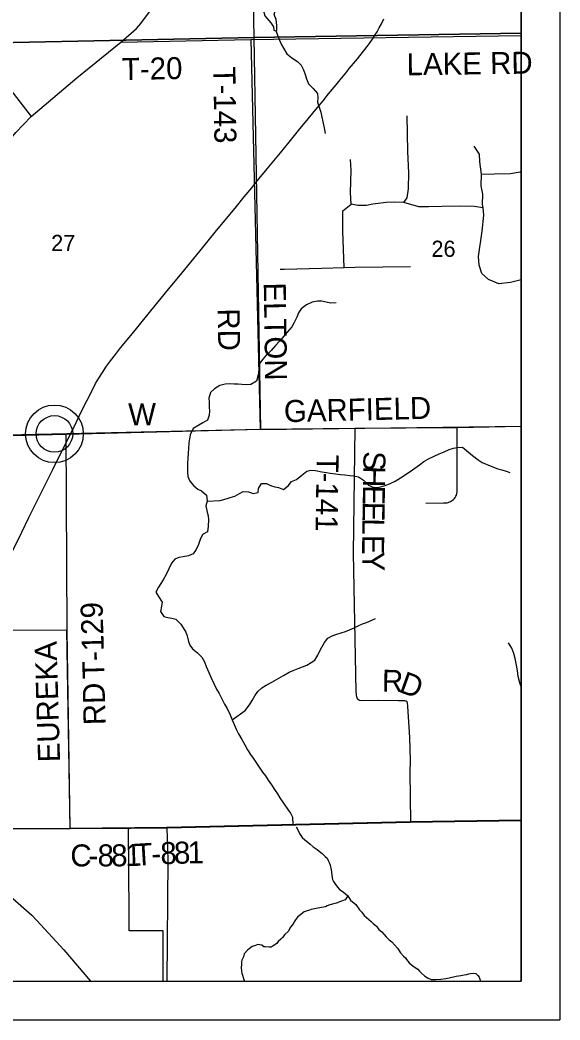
# Model space of a CAD drawing. Extents: x 0 to 36.9, y 0 to 22.
# Drawn here: x 7.606 to 9, y 14 to 16.582 of the extents above; entities that cross this region are included whole.
import ezdxf

# ---------------------------------------------------------------- set-up
doc = ezdxf.new("R2010")
doc.units = 0
for name, color, linetype in [('Default', 7, 'Continuous'), ('GM_X_County_Road', 7, 'Continuous'), ('GM_X_County_Road_Text', 7, 'Continuous'), ('GM_X_Minor_Lake', 7, 'Continuous'), ('GM_X_Minor_River', 7, 'Continuous'), ('GM_X_Rail_Line', 7, 'Continuous'), ('GM_X_Section', 7, 'Continuous'), ('GM_X_Section_Text', 7, 'Continuous'), ('GM_X_State_Route', 7, 'Continuous'), ('GM_X_Township_Road', 7, 'Continuous'), ('GM_X_Township_Road_Text', 7, 'Continuous'), ('GM_X_Unincorporated', 7, 'Continuous'), ('GM_X_Unincorporated_Location', 7, 'Continuous'), ('SH_Cut_Line', 7, 'Continuous'), ('SH_Data', 7, 'Continuous')]:
    doc.layers.add(name, color=color, linetype=linetype)

msp = doc.modelspace()

# ---------------------------------------------------------------- linework, layer by layer
at = {"layer": 'Default'}
for points in [[(8.9, 16.5477), (8.9, 17.5601), (8.1912, 17.5487), (8.21, 16.5368)], [(8.9, 15.5336), (8.9, 16.5477), (8.21, 16.5368), (8.2269, 15.5248)]]:
    msp.add_lwpolyline(points, close=True, dxfattribs=at)
msp.add_lwpolyline([(6.5942, 14.1), (7.9756, 14.1), (7.9756, 14.2298), (7.8885, 14.2299), (7.8885, 14.2755), (7.8862, 14.4955), (7.7356, 14.4946), (7.7276, 15.0066), (7.4716, 15.0059)], dxfattribs=at)
at = {"layer": 'GM_X_County_Road'}
for p, q in [((7.4756, 15.5061), (7.7254, 15.5123)), ((8.6139, 14.511), (8.9, 14.5152)), ((7.4323, 14.4931), (7.7358, 14.4941)), ((7.7358, 14.4941), (7.8934, 14.4956))]:
    msp.add_line(p, q, dxfattribs=at)
for points in [[(7.5431, 17.5191), (7.5334, 17.2126), (7.5226, 16.9418), (7.5085, 16.6619), (7.5038, 16.5816), (7.5026, 16.5512), (7.5032, 16.5386), (7.5044, 16.52), (7.56, 16.4312), (7.6351, 16.3326)], [(7.7254, 15.5123), (8.2259, 15.5257), (8.4702, 15.5284), (8.7347, 15.5299), (8.9, 15.5336)], [(7.8934, 14.4956), (7.9821, 14.4964), (7.986, 14.4965), (8.6139, 14.511)]]:
    msp.add_lwpolyline(points, dxfattribs=at)
at = {"layer": 'GM_X_Minor_Lake'}
msp.add_lwpolyline([(8.2296, 16.6219), (8.2341, 16.6091), (8.2385, 16.5928), (8.2537, 16.5745), (8.2607, 16.5647), (8.2616, 16.556), (8.2696, 16.5535), (8.269, 16.5679), (8.2676, 16.5831), (8.2624, 16.5963), (8.2649, 16.6058), (8.2666, 16.6135), (8.2642, 16.6195)], dxfattribs=at)
at = {"layer": 'GM_X_Minor_River'}
for points in [[(8.2671, 16.5543), (8.2741, 16.5339), (8.2808, 16.5199), (8.2867, 16.509), (8.2953, 16.4948), (8.3081, 16.484), (8.323, 16.4747), (8.3323, 16.465), (8.3382, 16.4534), (8.3423, 16.4409), (8.3455, 16.4296), (8.3507, 16.4168), (8.363, 16.4048), (8.3743, 16.3925), (8.3748, 16.3819), (8.3739, 16.3697), (8.3787, 16.3565), (8.3824, 16.3437), (8.3852, 16.3308), (8.3877, 16.3187), (8.3918, 16.3036), (8.394, 16.2888)], [(8.4223, 15.8513), (8.4079, 15.8506), (8.3969, 15.8535), (8.3843, 15.8563), (8.3744, 15.8561), (8.3604, 15.8532), (8.3461, 15.8461), (8.3318, 15.8364), (8.3248, 15.826), (8.3208, 15.8149), (8.3143, 15.8008), (8.308, 15.7893), (8.2961, 15.7761), (8.2872, 15.7657), (8.276, 15.753), (8.266, 15.7411), (8.2548, 15.7283), (8.2421, 15.7163), (8.2328, 15.7059), (8.2246, 15.6952), (8.2226, 15.6792), (8.2214, 15.6659), (8.2171, 15.6495), (8.2021, 15.6405), (8.1899, 15.6403), (8.1793, 15.6412), (8.1698, 15.6418), (8.1595, 15.6416), (8.1462, 15.6425), (8.1356, 15.6419), (8.1224, 15.6379), (8.1085, 15.6297), (8.0984, 15.62), (8.0941, 15.6055), (8.095, 15.5949), (8.0949, 15.5824), (8.0951, 15.5718), (8.0949, 15.5619), (8.0902, 15.5485), (8.0785, 15.5415), (8.0676, 15.536), (8.0537, 15.527), (8.0457, 15.5109), (8.0422, 15.49), (8.0414, 15.4751), (8.0408, 15.4641), (8.0395, 15.4497), (8.039, 15.4379), (8.0384, 15.4265), (8.0387, 15.4144), (8.0392, 15.4037), (8.0448, 15.3913), (8.0548, 15.3794), (8.0656, 15.3704), (8.0752, 15.3661), (8.0879, 15.3553), (8.0897, 15.3394), (8.0861, 15.3279), (8.0895, 15.3113), (8.0923, 15.3015), (8.0932, 15.2916), (8.0924, 15.2749), (8.09, 15.2604), (8.0772, 15.2534), (8.0714, 15.2407), (8.0674, 15.2281), (8.0612, 15.2144), (8.0531, 15.2032), (8.0414, 15.1981), (8.0278, 15.1955), (8.0164, 15.1938), (8.0058, 15.1895), (7.9977, 15.1798), (7.9907, 15.1649), (7.9834, 15.1503), (7.9757, 15.1362), (7.9642, 15.1174), (7.9569, 15.1043), (7.9639, 15.0934), (7.9733, 15.0784), (7.9719, 15.0685), (7.9691, 15.0548), (7.9773, 15.0421), (7.9884, 15.0388), (7.9979, 15.0375), (8.009, 15.0347), (8.0214, 15.022), (8.0276, 15.0122), (8.0343, 15.0017), (8.0379, 14.9915), (8.0411, 14.9775), (8.0444, 14.9677), (8.0517, 14.958), (8.0648, 14.9484), (8.076, 14.9372), (8.0823, 14.9251), (8.0871, 14.9123), (8.0942, 14.8973), (8.0998, 14.8833), (8.1065, 14.869), (8.114, 14.8544)], [(8.0897, 15.3394), (8.1231, 15.3415), (8.1386, 15.3459), (8.1492, 15.3488), (8.1613, 15.3528), (8.1729, 15.3595), (8.1827, 15.3649), (8.196, 15.3633), (8.2086, 15.359), (8.2215, 15.3618), (8.2217, 15.3721), (8.2298, 15.3851), (8.2427, 15.3854), (8.2531, 15.3799), (8.2645, 15.377), (8.274, 15.3753), (8.2863, 15.3695), (8.2986, 15.3792), (8.3075, 15.3907), (8.3196, 15.3951), (8.3335, 15.4064), (8.3469, 15.4168), (8.3572, 15.4193), (8.3689, 15.4184), (8.3853, 15.4153), (8.3971, 15.4136), (8.407, 15.4122), (8.4204, 15.4102), (8.4337, 15.4085), (8.4447, 15.4072), (8.458, 15.4055), (8.4675, 15.405), (8.4801, 15.4025), (8.4928, 15.394), (8.5055, 15.3813), (8.5197, 15.3751), (8.533, 15.3761), (8.5462, 15.3794), (8.5602, 15.3842), (8.5745, 15.3913), (8.588, 15.3995), (8.6135, 15.4159), (8.6251, 15.4245), (8.6371, 15.4338), (8.6488, 15.4416), (8.6604, 15.4486), (8.6751, 15.4561), (8.6886, 15.462), (8.7007, 15.4672), (8.7139, 15.4727), (8.7252, 15.4763), (8.7354, 15.478), (8.7483, 15.4794), (8.7641, 15.466), (8.7738, 15.4571), (8.7888, 15.446), (8.7988, 15.4397), (8.8091, 15.4353), (8.8237, 15.4291), (8.8393, 15.4233), (8.8496, 15.4205), (8.8607, 15.4169), (8.8706, 15.414)], [(8.1541, 14.7754), (8.1879, 14.7995), (8.199, 14.8141), (8.2056, 14.8245), (8.2123, 14.8368), (8.2204, 14.8479), (8.2309, 14.8576), (8.2414, 14.8642), (8.2564, 14.8721), (8.2688, 14.8788), (8.2865, 14.8893), (8.3015, 14.8983), (8.3117, 14.9027), (8.3241, 14.9075), (8.3355, 14.9118), (8.3464, 14.9162), (8.3577, 14.9229), (8.3674, 14.9291), (8.3752, 14.9418), (8.3796, 14.9513), (8.3858, 14.9625), (8.392, 14.9751), (8.4006, 14.9855), (8.4122, 14.9922), (8.4243, 14.9958), (8.4349, 14.9994), (8.4462, 15.0034), (8.4568, 15.0074), (8.4692, 15.0129), (8.4794, 15.0176), (8.4907, 15.0228), (8.5005, 15.0267), (8.5125, 15.0319), (8.5235, 15.037)], [(8.9, 14.8599), (8.8963, 14.8702), (8.8922, 14.8865), (8.89, 14.9024), (8.8867, 14.9201), (8.8842, 14.933), (8.8809, 14.9462), (8.8757, 14.9598), (8.8671, 14.9741)], [(8.114, 14.8544), (8.1206, 14.8427), (8.1265, 14.8311), (8.1344, 14.8153), (8.1407, 14.804), (8.1486, 14.7878), (8.1541, 14.7754), (8.1593, 14.7629), (8.164, 14.7509), (8.1703, 14.7385), (8.1786, 14.7242), (8.1864, 14.7107), (8.1935, 14.6979), (8.2009, 14.6859), (8.2083, 14.6758), (8.2165, 14.6634), (8.2251, 14.6506), (8.2325, 14.6401), (8.2399, 14.63), (8.2465, 14.6195), (8.2551, 14.6071), (8.2633, 14.5948), (8.2707, 14.5839), (8.2769, 14.5738), (8.2879, 14.5576), (8.2976, 14.5438), (8.3042, 14.5336), (8.3094, 14.5235), (8.3107, 14.5035)], [(8.3191, 14.4987), (8.3259, 14.4858), (8.3279, 14.4812), (8.331, 14.4764), (8.3349, 14.4715), (8.3411, 14.4648), (8.3496, 14.4588), (8.355, 14.454), (8.3627, 14.4473), (8.3731, 14.4406), (8.3785, 14.4362), (8.3866, 14.4298), (8.3936, 14.422), (8.399, 14.4175), (8.4021, 14.4115), (8.4041, 14.4066), (8.4065, 14.3994), (8.4098, 14.388), (8.4108, 14.3748), (8.4117, 14.3672), (8.4133, 14.3626), (8.4157, 14.3573), (8.4188, 14.3525), (8.4259, 14.3427), (8.4313, 14.3371), (8.4382, 14.333), (8.4459, 14.3267), (8.4525, 14.3207), (8.4595, 14.3095), (8.4731, 14.2979), (8.4828, 14.2848), (8.4883, 14.278), (8.4949, 14.2702), (8.5123, 14.2541), (8.5181, 14.2493), (8.5265, 14.2426), (8.5324, 14.234), (8.5401, 14.2277), (8.5514, 14.2149), (8.5595, 14.2067), (8.5661, 14.2019), (8.5731, 14.1937), (8.5804, 14.1854), (8.5883, 14.1738), (8.596, 14.1648), (8.601, 14.1607), (8.6038, 14.1562), (8.6108, 14.1479), (8.6212, 14.1394), (8.6331, 14.1316), (8.6378, 14.1264), (8.6428, 14.1211), (8.6502, 14.1141), (8.6556, 14.1104), (8.6602, 14.1078), (8.6678, 14.1049), (8.6792, 14.1043), (8.6929, 14.1057), (8.7054, 14.1075), (8.7141, 14.1088), (8.7319, 14.1129), (8.7444, 14.1151), (8.7527, 14.1164), (8.7595, 14.1176), (8.7645, 14.1189), (8.7694, 14.1197), (8.7766, 14.121), (8.7831, 14.12), (8.7877, 14.1151), (8.7912, 14.1102), (8.7928, 14.1053), (8.795, 14.1)], [(8.4525, 14.3207), (8.4459, 14.31), (8.4364, 14.3064), (8.4311, 14.3047), (8.4255, 14.3027), (8.4062, 14.297), (8.399, 14.295), (8.3945, 14.2926), (8.3847, 14.2906), (8.3801, 14.2897), (8.3748, 14.2885), (8.3582, 14.2855), (8.3536, 14.2835), (8.3449, 14.2814), (8.3397, 14.2794), (8.3318, 14.2732), (8.3228, 14.2654), (8.3176, 14.2585), (8.3143, 14.2538), (8.3121, 14.2492), (8.3073, 14.2434), (8.3028, 14.2373), (8.2992, 14.2292), (8.2899, 14.221), (8.2843, 14.2129), (8.2798, 14.2087), (8.2731, 14.2028), (8.2694, 14.1974), (8.26, 14.1912), (8.2548, 14.188), (8.2494, 14.1883), (8.2403, 14.1885), (8.2354, 14.1888), (8.2307, 14.1929), (8.2204, 14.1946), (8.214, 14.1926), (8.2057, 14.1898), (8.1978, 14.1835), (8.1933, 14.1804), (8.1852, 14.1711), (8.183, 14.1635), (8.179, 14.1543), (8.1784, 14.1493), (8.1777, 14.1436), (8.1775, 14.1356), (8.1784, 14.1265), (8.1793, 14.1212), (8.1853, 14.1019), (8.186, 14.1)]]:
    msp.add_lwpolyline(points, dxfattribs=at)
at = {"layer": 'GM_X_Rail_Line'}
for points in [[(5.2462, 14.4712), (5.4467, 14.4748), (5.4581, 14.475), (5.4676, 14.4751), (5.9207, 14.4754), (6.4063, 14.4846), (6.5807, 14.485), (6.7336, 14.4854), (6.7812, 14.4863), (6.8569, 14.4852), (7.1313, 14.488), (7.4027, 14.4935), (7.7356, 14.4946), (7.9858, 14.497), (8.6137, 14.5116), (8.9, 14.5158), (8.9, 20.5927)], [(7.5796, 15.195), (7.6115, 15.2595), (7.6295, 15.2973), (7.6905, 15.4195), (7.7174, 15.4737), (7.7348, 15.5092), (7.7523, 15.5443), (7.7673, 15.575), (7.779, 15.5987), (7.7915, 15.6236), (7.8016, 15.643), (7.8101, 15.6575), (7.8192, 15.6722), (7.8298, 15.6881), (7.8399, 15.702), (7.8525, 15.7184), (7.8657, 15.7351), (7.8966, 15.7728), (7.9444, 15.8311), (7.99, 15.8867), (8.0162, 15.919), (8.0704, 15.9851), (8.1139, 16.0382), (8.1614, 16.096), (8.1852, 16.1252), (8.2044, 16.1487), (8.2196, 16.1675), (8.2443, 16.1975), (8.2612, 16.2179), (8.2786, 16.2391), (8.3007, 16.2662), (8.3255, 16.2965), (8.3502, 16.3269), (8.3744, 16.3564), (8.3885, 16.3736), (8.4027, 16.391), (8.4223, 16.4149), (8.4324, 16.4273), (8.4411, 16.4377), (8.4498, 16.4484), (8.4562, 16.4565), (8.4672, 16.4695), (8.4774, 16.482), (8.5026, 16.5134), (8.5104, 16.524), (8.5162, 16.5323), (8.5226, 16.5424), (8.5278, 16.551), (8.5337, 16.5618), (8.5393, 16.5724), (8.5452, 16.5853)]]:
    msp.add_lwpolyline(points, dxfattribs=at)
msp.add_lwpolyline([(4.2643, 14.1), (8.9, 14.1), (8.9, 14.5158), (8.6137, 14.5116), (7.9858, 14.497), (7.7356, 14.4946), (7.4027, 14.4935), (7.1313, 14.488), (6.8569, 14.4852), (6.7812, 14.4863), (6.7336, 14.4854), (6.5807, 14.485), (6.4063, 14.4846), (5.9207, 14.4754), (5.4676, 14.4751), (5.4581, 14.475), (5.4467, 14.4748), (5.2462, 14.4712), (5.1185, 14.4712), (4.6008, 14.4672), (4.262, 14.4619)], close=True, dxfattribs=at)
at = {"layer": 'GM_X_Section'}
for points in [[(8.1912, 17.5487), (8.21, 16.5368), (7.2171, 16.5161), (7.1983, 17.5272)], [(7.2171, 16.5161), (8.21, 16.5368), (8.2269, 15.5248), (7.2257, 15.5025)]]:
    msp.add_lwpolyline(points, close=True, dxfattribs=at)
at = {"layer": 'GM_X_State_Route'}
for points in [[(7.0471, 15.4964), (7.1457, 15.6437), (7.2273, 15.7704), (7.2856, 15.8706), (7.332, 15.9464), (7.3892, 16.0334), (7.428, 16.0996), (7.4971, 16.1868), (7.5585, 16.2465), (7.5956, 16.2915), (7.6351, 16.3326), (7.7529, 16.4322), (7.8671, 16.5247), (7.9067, 16.5599), (7.9185, 16.5733), (7.9403, 16.6034)], [(7.3495, 14.4465), (7.3797, 14.4373), (7.4541, 14.4024), (7.5306, 14.3574), (7.5811, 14.3201), (7.6368, 14.2708), (7.6497, 14.2567), (7.7192, 14.1808), (7.7888, 14.1)]]:
    msp.add_lwpolyline(points, dxfattribs=at)
at = {"layer": 'GM_X_Township_Road'}
for p, q in [((8.202, 16.5313), (8.2259, 15.5257)), ((7.7278, 15.008), (7.7254, 15.5123)), ((8.6139, 14.511), (8.9, 14.5152)), ((7.4323, 14.4931), (7.7358, 14.4941)), ((7.7358, 14.4941), (7.8934, 14.4956))]:
    msp.add_line(p, q, dxfattribs=at)
for points in [[(7.8671, 16.5247), (8.202, 16.5313), (8.9, 16.5418)], [(8.5971, 16.1107), (8.6053, 16.1224), (8.6088, 16.1458), (8.6101, 16.1871), (8.6074, 16.2421), (8.6053, 16.3343)], [(8.7971, 16.1841), (8.7931, 16.216), (8.7924, 16.2359), (8.7781, 16.2563)], [(8.8017, 16.0968), (8.7787, 16.1007), (8.7401, 16.1011), (8.6947, 16.1004), (8.6603, 16.0997), (8.6356, 16.0997), (8.5971, 16.1107), (8.5737, 16.1114), (8.5517, 16.1107), (8.5173, 16.1066), (8.5005, 16.1034), (8.478, 16.1034), (8.4609, 16.1066), (8.4595, 16.1368), (8.4615, 16.1946), (8.4595, 16.2221)], [(8.9, 15.9114), (8.8723, 15.9045), (8.8419, 15.9007), (8.8153, 15.9121), (8.7986, 15.9273), (8.7918, 15.9486), (8.7895, 15.9714), (8.7994, 16.0367), (8.8032, 16.0778), (8.8017, 16.0968), (8.8001, 16.1059), (8.8009, 16.1325), (8.7963, 16.1537), (8.7971, 16.1841), (8.8305, 16.1849), (8.8723, 16.1857), (8.8974, 16.1895), (8.9, 16.19)], [(8.4428, 15.9428), (8.4398, 16.0364), (8.4398, 16.0792), (8.4398, 16.0888), (8.4609, 16.1066)], [(8.2781, 15.9382), (8.2886, 15.9386), (8.3855, 15.9411), (8.4428, 15.9428), (8.4716, 15.9437), (8.614, 15.9455)], [(8.4702, 15.5284), (8.4663, 15.2055), (8.4732, 14.849), (8.4742, 14.8376), (8.4746, 14.8354), (8.4754, 14.8323), (8.4766, 14.8305), (8.4777, 14.829), (8.48, 14.8271), (8.4823, 14.826), (8.4869, 14.8253), (8.5312, 14.8256), (8.583, 14.8253), (8.5986, 14.8248), (8.601, 14.8244), (8.6031, 14.8237), (8.6041, 14.8231), (8.6047, 14.8223), (8.6051, 14.8213), (8.6055, 14.8196), (8.6068, 14.8098), (8.6119, 14.7298), (8.6136, 14.6703), (8.6126, 14.6395), (8.6139, 14.511)], [(8.6534, 15.3345), (8.6994, 15.3352), (8.7024, 15.3351), (8.7053, 15.3352), (8.7086, 15.3356), (8.7114, 15.3363), (8.7149, 15.3375), (8.7175, 15.3387), (8.7204, 15.3404), (8.7228, 15.3422), (8.7252, 15.3443), (8.7274, 15.3467), (8.7292, 15.349), (8.7313, 15.3524), (8.7325, 15.3552), (8.734, 15.3597), (8.7348, 15.3638), (8.7349, 15.3672), (8.7346, 15.3716), (8.7347, 15.5299)], [(7.7358, 14.4941), (7.7278, 15.0061), (7.7278, 15.008)], [(7.8934, 14.4956), (7.9821, 14.4964), (7.986, 14.4965), (8.6139, 14.511)], [(7.9863, 14.1), (7.9887, 14.4139), (7.986, 14.4965)]]:
    msp.add_lwpolyline(points, dxfattribs=at)
at = {"layer": 'GM_X_Unincorporated'}
for radius in [0.0744, 0.0472]:
    msp.add_circle((7.6954, 15.5134), radius, dxfattribs=at)
at = {"layer": 'GM_X_Unincorporated_Location'}
msp.add_line((7.6954, 15.5134), (7.6954, 15.5134), dxfattribs=at)
at = {"layer": 'SH_Cut_Line'}
for points in [[(5.2462, 14.4712), (5.4467, 14.4748), (5.4581, 14.475), (5.4676, 14.4751), (5.9207, 14.4754), (6.4063, 14.4846), (6.5807, 14.485), (6.7336, 14.4854), (6.7812, 14.4863), (6.8569, 14.4852), (7.1313, 14.488), (7.4027, 14.4935), (7.7356, 14.4946), (7.9858, 14.497), (8.6137, 14.5116), (8.9, 14.5158), (8.9, 20.9)], [(2.1, 14.1), (8.9, 14.1), (8.9, 14.5158), (8.6137, 14.5116), (7.9858, 14.497), (7.7356, 14.4946), (7.4027, 14.4935), (7.1313, 14.488), (6.8569, 14.4852), (6.7812, 14.4863), (6.7336, 14.4854), (6.5807, 14.485), (6.4063, 14.4846), (5.9207, 14.4754), (5.4676, 14.4751), (5.4581, 14.475), (5.4467, 14.4748), (5.2462, 14.4712)]]:
    msp.add_lwpolyline(points, dxfattribs=at)
at = {"layer": 'SH_Data'}
for p, q in [((9, 21), (9, 14)), ((8.9, 20.9), (8.9, 14.1)), ((2.1, 14.1), (8.9, 14.1)), ((2, 14), (9, 14))]:
    msp.add_line(p, q, dxfattribs=at)

# ---------------------------------------------------------------- texts
at = {"layer": 'GM_X_County_Road_Text'}
for s, height, rotation, p in [('GARFIELD', 0.05682, 1.3576, (8.2882, 15.5434)), ('W', 0.0568, 0.7248, (7.8862, 15.5351)), ('C', 0.0568, 0.0039, (7.7365, 14.3965)), ('8', 0.0568, 0.12, (7.8067, 14.3966)), ('8', 0.0568, 0.4782, (7.842, 14.3966)), ('1', 0.0568, 1.8865, (7.8786, 14.397)), ('-', 0.0568, 0.0233, (7.7832, 14.3965))]:
    msp.add_text(s, height=height, rotation=rotation, dxfattribs=at).set_placement(p)
at = {"layer": 'GM_X_Section_Text'}
for s, p in [('27', (7.6869, 15.9853)), ('26', (8.6682, 15.9703))]:
    msp.add_text(s, height=0.04186, rotation=0, dxfattribs=at).set_placement(p)
at = {"layer": 'GM_X_Township_Road_Text'}
for s, height, rotation, p in [('LAKE RD', 0.05682, 0.7981, (8.6046, 16.439)), ('T-20', 0.05682, 1.061, (7.87, 16.4267)), ('T-143', 0.05682, 270.8431, (8.1054, 16.4613)), ('ELTON', 0.05682, 270.839, (8.2355, 15.9039)), ('RD', 0.05682, 270.9872, (8.1164, 15.8369)), ('T-141', 0.05682, 269.1579, (8.3721, 15.46)), ('S', 0.0568, 269.0972, (8.493, 15.4691)), ('H', 0.0568, 269.0965, (8.4924, 15.4307)), ('E', 0.0568, 269.0957, (8.4917, 15.3808)), ('E', 0.0568, 269.0959, (8.491, 15.3383)), ('L', 0.0568, 269.1111, (8.4903, 15.2957)), ('E', 0.0568, 269.616, (8.4896, 15.2527)), ('Y', 0.0568, 271.3004, (8.4894, 15.2084)), ('T-129', 0.05682, 91.6848, (7.8251, 14.8815)), ('EUREKA', 0.05682, 91.695, (7.71, 14.6663)), ('R', 0.0568, 359.0281, (8.5401, 14.8476)), ('D', 0.0568, 340.2575, (8.582, 14.8477)), ('RD', 0.05682, 91.4807, (7.8275, 14.762)), ('8', 0.0568, 2.1342, (7.9697, 14.4019)), ('8', 0.0568, 1.3479, (8.0045, 14.4032)), ('1', 0.0568, 1.0305, (8.0394, 14.404)), ('T', 0.0568, 3.4862, (7.9043, 14.3981)), ('-', 0.0568, 2.8737, (7.9466, 14.4007))]:
    msp.add_text(s, height=height, rotation=rotation, dxfattribs=at).set_placement(p)

doc.saveas('drawing.dxf')
